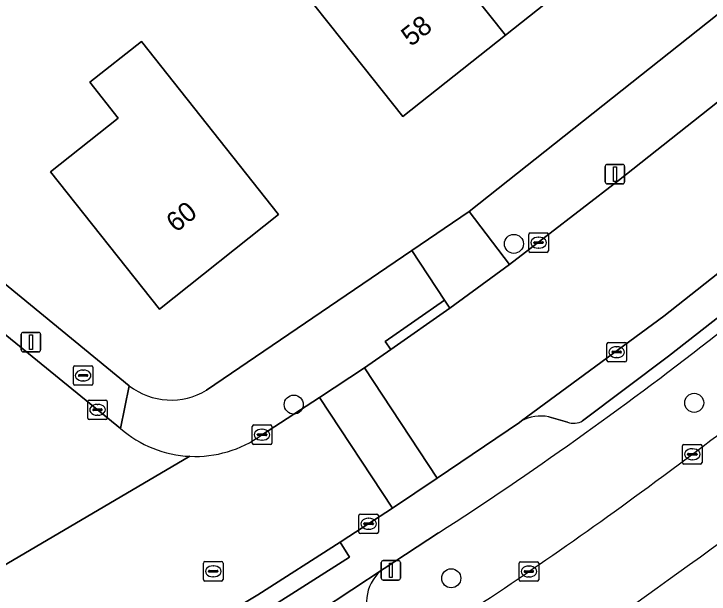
# Model space of a CAD drawing. Extents: x 159499 to 160349, y 382524 to 383273.
# Drawn here: x 159751.59 to 159787.26, y 382966.02 to 382995.78 of the extents above; entities that cross this region are included whole.
import ezdxf

# ---------------------------------------------------------------- set-up
doc = ezdxf.new("R2010")
doc.units = 0
for name, color, linetype in [('IMGEO_Boom', 7, 'Continuous'), ('IMGEO_Brandkraan', 7, 'Continuous'), ('IMGEO_Erf', 7, 'Continuous'), ('IMGEO_Groenvoorziening', 7, 'Continuous'), ('IMGEO_Kolk', 7, 'Continuous'), ('IMGEO_Lichtmast', 7, 'Continuous'), ('IMGEO_Pand', 7, 'Continuous'), ('IMGEO_Pand_nummerreeks', 7, 'Continuous'), ('IMGEO_Parkeervlak_open', 7, 'Continuous'), ('IMGEO_Rijbaan_lokaal_open', 7, 'Continuous'), ('IMGEO_Rioolput', 7, 'Continuous'), ('IMGEO_Voetpad_open', 7, 'Continuous')]:
    doc.layers.add(name, color=color, linetype=linetype)

msp = doc.modelspace()

# ---------------------------------------------------------------- linework, layer by layer
at = {"layer": 'IMGEO_Boom'}
for centre in [(159777.246, 382983.98), (159765.949, 382975.736), (159786.498, 382975.827), (159774.031, 382966.825)]:
    msp.add_circle(centre, 0.489, dxfattribs=at)
at = {"layer": 'IMGEO_Brandkraan'}
for p, q in [((159754.641, 382976.804), (159754.641, 382977.656)), ((159754.716, 382977.73), (159755.568, 382977.73)), ((159755.129, 382977.51), (159755.154, 382977.51)), ((159755.642, 382977.656), (159755.642, 382976.804)), ((159754.9, 382977.224), (159754.9, 382977.236)), ((159755.338, 382977.187), (159754.94, 382977.187)), ((159754.943, 382977.273), (159755.341, 382977.273)), ((159755.384, 382977.236), (159755.384, 382977.224)), ((159755.152, 382976.95), (159755.127, 382976.95)), ((159755.568, 382976.73), (159754.716, 382976.73))]:
    msp.add_line(p, q, dxfattribs=at)
for points in [[(159754.641, 382976.804), (159754.641, 382977.656)], [(159754.716, 382977.73), (159755.568, 382977.73)], [(159755.642, 382977.656), (159755.642, 382976.804)], [(159755.568, 382976.73), (159754.716, 382976.73)]]:
    msp.add_lwpolyline(points, dxfattribs=at)
for centre, radius, start, end in [((159754.718, 382977.654), 0.0765, 91.552, 178.448), ((159754.718, 382977.654), 0.0765, 91.552, 178.448), ((159755.566, 382977.654), 0.0765, 1.552, 88.448), ((159755.566, 382977.654), 0.0765, 1.552, 88.448), ((159754.94, 382977.233), 0.0403, 85.8775, 175.7526), ((159754.937, 382977.223), 0.0366, 178.938, 274.7102), ((159755.341, 382977.23), 0.043, 264.8664, 352.4533), ((159755.345, 382977.235), 0.0386, 1.7309, 96.639), ((159754.718, 382976.806), 0.0765, 181.552, 268.448), ((159754.718, 382976.806), 0.0765, 181.552, 268.448), ((159755.566, 382976.806), 0.0765, 271.552, 358.448), ((159755.566, 382976.806), 0.0765, 271.552, 358.448)]:
    msp.add_arc(centre, radius, start, end, dxfattribs=at)
for centre, major_axis, ratio, start_param, end_param in [((159755.128, 382977.23), (-0.387, 0.002), 0.722429, 4.712389, 7.853982), ((159755.153, 382977.23), (-0.39, 0.002), 0.717154, 1.570796, 4.712389)]:
    msp.add_ellipse(centre, major_axis=major_axis, ratio=ratio, start_param=start_param, end_param=end_param, dxfattribs=at)
at = {"layer": 'IMGEO_Erf'}
for points in [[(159761.473, 382976.471), (159772.008, 382983.648), (159774.942, 382985.649), (159793.053, 383000), (159824.858, 383025.202)], [(159738.574, 382992.221), (159738.857, 382991.989), (159741.629, 382989.716), (159757.507, 382976.697)]]:
    msp.add_lwpolyline(points, dxfattribs=at)
for points in [[(159779.201, 383007.202), (159776.897, 383005.374), (159778.957, 383002.782), (159779.951, 383001.528), (159781.162, 383000), (159782.063, 382998.864), (159776.807, 382994.694), (159771.548, 382990.52), (159768.44, 382994.437), (159765.495, 382998.147), (159764.202, 382999.777), (159764.479, 383000), (159766.41, 383001.552), (159769.487, 383003.92), (159772.486, 383006.228), (159772.407, 383006.327), (159774.63, 383008.091), (159772.911, 383010.258), (159775.283, 383012.14)], [(159765.175, 382985.49), (159759.06, 382980.638), (159753.471, 382987.681), (159756.943, 382990.435), (159755.486, 382992.271), (159758.129, 382994.368)]]:
    msp.add_lwpolyline(points, close=True, dxfattribs=at)
for centre, radius, start, end in [((159759.657, 382979.51), 3.54, 232.6136, 300.8636), ((159604.996, 383217.908), 309.102, 303.12927, 307.16526)]:
    msp.add_arc(centre, radius, start, end, dxfattribs=at)
at = {"layer": 'IMGEO_Groenvoorziening'}
msp.add_lwpolyline([(159773.383, 382969.151), (159770.582, 382967.334)], dxfattribs=at)
for centre, radius, start, end in [((159553.608, 383284.554), 388.767, 306.36737, 308.73678), ((159667.805, 383132.244), 194.283, 302.91697, 307.94175), ((159666.675, 383130.798), 197.913, 302.42764, 306.40373), ((159771.795, 382965.603), 2.113, 125.024, 298.4917)]:
    msp.add_arc(centre, radius, start, end, dxfattribs=at)
at = {"layer": 'IMGEO_Kolk'}
for p, q in [((159778.012, 382983.616), (159778.012, 382984.468)), ((159778.087, 382984.542), (159778.939, 382984.542)), ((159778.5, 382984.322), (159778.525, 382984.322)), ((159779.013, 382984.468), (159779.013, 382983.616)), ((159778.271, 382984.036), (159778.271, 382984.048)), ((159778.709, 382983.999), (159778.311, 382983.999)), ((159778.314, 382984.085), (159778.712, 382984.085)), ((159778.755, 382984.048), (159778.755, 382984.036)), ((159778.523, 382983.762), (159778.498, 382983.762)), ((159778.939, 382983.542), (159778.087, 382983.542)), ((159782.094, 382978.927), (159782.946, 382978.927)), ((159782.019, 382978.001), (159782.019, 382978.853)), ((159782.507, 382978.707), (159782.532, 382978.707)), ((159783.02, 382978.853), (159783.02, 382978.001)), ((159782.278, 382978.421), (159782.278, 382978.433)), ((159782.716, 382978.384), (159782.318, 382978.384)), ((159782.321, 382978.47), (159782.719, 382978.47)), ((159782.762, 382978.433), (159782.762, 382978.421)), ((159782.946, 382977.927), (159782.094, 382977.927)), ((159782.53, 382978.147), (159782.505, 382978.147)), ((159755.379, 382975.042), (159755.379, 382975.894)), ((159755.454, 382975.968), (159756.306, 382975.968)), ((159755.867, 382975.748), (159755.892, 382975.748)), ((159756.38, 382975.894), (159756.38, 382975.042)), ((159755.638, 382975.462), (159755.638, 382975.474)), ((159756.076, 382975.425), (159755.678, 382975.425)), ((159755.681, 382975.511), (159756.079, 382975.511)), ((159756.122, 382975.474), (159756.122, 382975.462)), ((159755.89, 382975.188), (159755.865, 382975.188)), ((159756.306, 382974.968), (159755.454, 382974.968)), ((159763.896, 382974.691), (159764.748, 382974.691)), ((159763.821, 382973.765), (159763.821, 382974.617)), ((159764.309, 382974.471), (159764.334, 382974.471)), ((159764.822, 382974.617), (159764.822, 382973.765)), ((159764.08, 382974.185), (159764.08, 382974.197)), ((159764.518, 382974.148), (159764.12, 382974.148)), ((159764.123, 382974.234), (159764.521, 382974.234)), ((159764.564, 382974.197), (159764.564, 382974.185)), ((159764.748, 382973.691), (159763.896, 382973.691)), ((159764.332, 382973.911), (159764.307, 382973.911)), ((159785.899, 382972.762), (159785.899, 382973.614)), ((159785.974, 382973.688), (159786.826, 382973.688)), ((159786.9, 382973.614), (159786.9, 382972.762)), ((159786.201, 382973.231), (159786.599, 382973.231)), ((159786.387, 382973.468), (159786.412, 382973.468)), ((159786.158, 382973.182), (159786.158, 382973.194)), ((159786.596, 382973.145), (159786.198, 382973.145)), ((159786.41, 382972.908), (159786.385, 382972.908)), ((159786.642, 382973.194), (159786.642, 382973.182)), ((159786.826, 382972.688), (159785.974, 382972.688)), ((159769.291, 382969.196), (159769.291, 382970.048)), ((159769.366, 382970.122), (159770.218, 382970.122)), ((159770.292, 382970.048), (159770.292, 382969.196)), ((159769.593, 382969.665), (159769.991, 382969.665)), ((159769.779, 382969.902), (159769.804, 382969.902)), ((159769.55, 382969.616), (159769.55, 382969.628)), ((159769.988, 382969.579), (159769.59, 382969.579)), ((159769.802, 382969.342), (159769.777, 382969.342)), ((159770.034, 382969.628), (159770.034, 382969.616)), ((159770.218, 382969.122), (159769.366, 382969.122)), ((159777.516, 382966.747), (159777.516, 382967.599)), ((159777.591, 382967.673), (159778.443, 382967.673)), ((159778.517, 382967.599), (159778.517, 382966.747)), ((159777.775, 382967.167), (159777.775, 382967.179)), ((159777.818, 382967.216), (159778.216, 382967.216)), ((159778.004, 382967.453), (159778.029, 382967.453)), ((159778.259, 382967.179), (159778.259, 382967.167)), ((159778.213, 382967.13), (159777.815, 382967.13)), ((159778.027, 382966.893), (159778.002, 382966.893)), ((159778.443, 382966.673), (159777.591, 382966.673))]:
    msp.add_line(p, q, dxfattribs=at)
for points in [[(159778.012, 382983.616), (159778.012, 382984.468)], [(159778.087, 382984.542), (159778.939, 382984.542)], [(159779.013, 382984.468), (159779.013, 382983.616)], [(159778.939, 382983.542), (159778.087, 382983.542)], [(159782.094, 382978.927), (159782.946, 382978.927)], [(159782.019, 382978.001), (159782.019, 382978.853)], [(159783.02, 382978.853), (159783.02, 382978.001)], [(159782.946, 382977.927), (159782.094, 382977.927)], [(159755.379, 382975.042), (159755.379, 382975.894)], [(159755.454, 382975.968), (159756.306, 382975.968)], [(159756.38, 382975.894), (159756.38, 382975.042)], [(159756.306, 382974.968), (159755.454, 382974.968)], [(159763.896, 382974.691), (159764.748, 382974.691)], [(159763.821, 382973.765), (159763.821, 382974.617)], [(159764.822, 382974.617), (159764.822, 382973.765)], [(159764.748, 382973.691), (159763.896, 382973.691)], [(159785.899, 382972.762), (159785.899, 382973.614)], [(159785.974, 382973.688), (159786.826, 382973.688)], [(159786.9, 382973.614), (159786.9, 382972.762)], [(159786.826, 382972.688), (159785.974, 382972.688)], [(159769.291, 382969.196), (159769.291, 382970.048)], [(159769.366, 382970.122), (159770.218, 382970.122)], [(159770.292, 382970.048), (159770.292, 382969.196)], [(159770.218, 382969.122), (159769.366, 382969.122)], [(159777.516, 382966.747), (159777.516, 382967.599)], [(159777.591, 382967.673), (159778.443, 382967.673)], [(159778.517, 382967.599), (159778.517, 382966.747)], [(159778.443, 382966.673), (159777.591, 382966.673)]]:
    msp.add_lwpolyline(points, dxfattribs=at)
for centre, radius, start, end in [((159778.089, 382984.466), 0.0765, 91.552, 178.448), ((159778.089, 382984.466), 0.0765, 91.552, 178.448), ((159778.937, 382984.466), 0.0765, 1.552, 88.448), ((159778.937, 382984.466), 0.0765, 1.552, 88.448), ((159778.311, 382984.045), 0.0403, 85.8775, 175.7526), ((159778.308, 382984.035), 0.0366, 178.938, 274.7102), ((159778.712, 382984.042), 0.043, 264.8664, 352.4533), ((159778.716, 382984.047), 0.0386, 1.7309, 96.639), ((159778.089, 382983.618), 0.0765, 181.552, 268.448), ((159778.089, 382983.618), 0.0765, 181.552, 268.448), ((159778.937, 382983.618), 0.0765, 271.552, 358.448), ((159778.937, 382983.618), 0.0765, 271.552, 358.448), ((159782.096, 382978.851), 0.0765, 91.552, 178.448), ((159782.096, 382978.851), 0.0765, 91.552, 178.448), ((159782.944, 382978.851), 0.0765, 1.552, 88.448), ((159782.944, 382978.851), 0.0765, 1.552, 88.448), ((159782.318, 382978.43), 0.0403, 85.8775, 175.7526), ((159782.315, 382978.42), 0.0366, 178.938, 274.7102), ((159782.719, 382978.427), 0.043, 264.8664, 352.4533), ((159782.723, 382978.432), 0.0386, 1.7309, 96.639), ((159782.096, 382978.003), 0.0765, 181.552, 268.448), ((159782.096, 382978.003), 0.0765, 181.552, 268.448), ((159782.944, 382978.003), 0.0765, 271.552, 358.448), ((159782.944, 382978.003), 0.0765, 271.552, 358.448), ((159755.456, 382975.892), 0.0765, 91.552, 178.448), ((159755.456, 382975.892), 0.0765, 91.552, 178.448), ((159756.304, 382975.892), 0.0765, 1.552, 88.448), ((159756.304, 382975.892), 0.0765, 1.552, 88.448), ((159755.678, 382975.471), 0.0403, 85.8775, 175.7526), ((159755.675, 382975.461), 0.0366, 178.938, 274.7102), ((159756.079, 382975.468), 0.043, 264.8664, 352.4533), ((159756.083, 382975.473), 0.0386, 1.7309, 96.639), ((159755.456, 382975.044), 0.0765, 181.552, 268.448), ((159755.456, 382975.044), 0.0765, 181.552, 268.448), ((159756.304, 382975.044), 0.0765, 271.552, 358.448), ((159756.304, 382975.044), 0.0765, 271.552, 358.448), ((159763.898, 382974.615), 0.0765, 91.552, 178.448), ((159763.898, 382974.615), 0.0765, 91.552, 178.448), ((159764.746, 382974.615), 0.0765, 1.552, 88.448), ((159764.746, 382974.615), 0.0765, 1.552, 88.448), ((159764.12, 382974.194), 0.0403, 85.8775, 175.7526), ((159764.117, 382974.184), 0.0366, 178.938, 274.7102), ((159764.521, 382974.191), 0.043, 264.8664, 352.4533), ((159764.525, 382974.196), 0.0386, 1.7309, 96.639), ((159763.898, 382973.767), 0.0765, 181.552, 268.448), ((159763.898, 382973.767), 0.0765, 181.552, 268.448), ((159764.746, 382973.767), 0.0765, 271.552, 358.448), ((159764.746, 382973.767), 0.0765, 271.552, 358.448), ((159785.976, 382973.612), 0.0765, 91.552, 178.448), ((159785.976, 382973.612), 0.0765, 91.552, 178.448), ((159786.824, 382973.612), 0.0765, 1.552, 88.448), ((159786.824, 382973.612), 0.0765, 1.552, 88.448), ((159786.198, 382973.191), 0.0403, 85.8775, 175.7526), ((159786.603, 382973.193), 0.0386, 1.7309, 96.639), ((159786.195, 382973.181), 0.0366, 178.938, 274.7102), ((159786.599, 382973.188), 0.043, 264.8664, 352.4533), ((159785.976, 382972.764), 0.0765, 181.552, 268.448), ((159785.976, 382972.764), 0.0765, 181.552, 268.448), ((159786.824, 382972.764), 0.0765, 271.552, 358.448), ((159786.824, 382972.764), 0.0765, 271.552, 358.448), ((159769.368, 382970.046), 0.0765, 91.552, 178.448), ((159769.368, 382970.046), 0.0765, 91.552, 178.448), ((159770.216, 382970.046), 0.0765, 1.552, 88.448), ((159770.216, 382970.046), 0.0765, 1.552, 88.448), ((159769.59, 382969.625), 0.0403, 85.8775, 175.7526), ((159769.995, 382969.627), 0.0386, 1.7309, 96.639), ((159769.587, 382969.615), 0.0366, 178.938, 274.7102), ((159769.991, 382969.622), 0.043, 264.8664, 352.4533), ((159769.368, 382969.198), 0.0765, 181.552, 268.448), ((159769.368, 382969.198), 0.0765, 181.552, 268.448), ((159770.216, 382969.198), 0.0765, 271.552, 358.448), ((159770.216, 382969.198), 0.0765, 271.552, 358.448), ((159777.593, 382967.597), 0.0765, 91.552, 178.448), ((159777.593, 382967.597), 0.0765, 91.552, 178.448), ((159778.441, 382967.597), 0.0765, 1.552, 88.448), ((159778.441, 382967.597), 0.0765, 1.552, 88.448), ((159777.815, 382967.176), 0.0403, 85.8775, 175.7526), ((159777.812, 382967.166), 0.0366, 178.938, 274.7102), ((159778.216, 382967.173), 0.043, 264.8664, 352.4533), ((159778.22, 382967.178), 0.0386, 1.7309, 96.639), ((159777.593, 382966.749), 0.0765, 181.552, 268.448), ((159777.593, 382966.749), 0.0765, 181.552, 268.448), ((159778.441, 382966.749), 0.0765, 271.552, 358.448), ((159778.441, 382966.749), 0.0765, 271.552, 358.448)]:
    msp.add_arc(centre, radius, start, end, dxfattribs=at)
for centre, major_axis, ratio, start_param, end_param in [((159778.499, 382984.042), (-0.387, 0.002), 0.722429, 4.712389, 7.853982), ((159778.524, 382984.042), (-0.39, 0.002), 0.717154, 1.570796, 4.712389), ((159782.506, 382978.427), (-0.387, 0.002), 0.722429, 4.712389, 7.853982), ((159782.531, 382978.427), (-0.39, 0.002), 0.717154, 1.570796, 4.712389), ((159755.866, 382975.468), (-0.387, 0.002), 0.722429, 4.712389, 7.853982), ((159755.891, 382975.468), (-0.39, 0.002), 0.717154, 1.570796, 4.712389), ((159764.308, 382974.191), (-0.387, 0.002), 0.722429, 4.712389, 7.853982), ((159764.333, 382974.191), (-0.39, 0.002), 0.717154, 1.570796, 4.712389), ((159786.386, 382973.188), (-0.387, 0.002), 0.722429, 4.712389, 7.853982), ((159786.411, 382973.188), (-0.39, 0.002), 0.717154, 1.570796, 4.712389), ((159769.778, 382969.622), (-0.387, 0.002), 0.722429, 4.712389, 7.853982), ((159769.803, 382969.622), (-0.39, 0.002), 0.717154, 1.570796, 4.712389), ((159778.003, 382967.173), (-0.387, 0.002), 0.722429, 4.712389, 7.853982), ((159778.028, 382967.173), (-0.39, 0.002), 0.717154, 1.570796, 4.712389)]:
    msp.add_ellipse(centre, major_axis=major_axis, ratio=ratio, start_param=start_param, end_param=end_param, dxfattribs=at)
at = {"layer": 'IMGEO_Lichtmast'}
for p, q in [((159781.934, 382987.156), (159781.934, 382987.956)), ((159781.934, 382987.956), (159781.934, 382987.156)), ((159782.034, 382988.056), (159782.824, 382988.056)), ((159782.824, 382988.056), (159782.034, 382988.056)), ((159782.924, 382987.956), (159782.924, 382987.156)), ((159782.924, 382987.156), (159782.924, 382987.956)), ((159782.824, 382987.056), (159782.034, 382987.056)), ((159782.034, 382987.056), (159782.824, 382987.056)), ((159751.966, 382978.54), (159751.966, 382979.34)), ((159751.966, 382979.34), (159751.966, 382978.54)), ((159752.066, 382979.44), (159752.856, 382979.44)), ((159752.856, 382979.44), (159752.066, 382979.44)), ((159752.956, 382979.34), (159752.956, 382978.54)), ((159752.956, 382978.54), (159752.956, 382979.34)), ((159752.856, 382978.44), (159752.066, 382978.44)), ((159752.066, 382978.44), (159752.856, 382978.44)), ((159770.436, 382966.833), (159770.436, 382967.633)), ((159770.436, 382967.633), (159770.436, 382966.833)), ((159770.536, 382967.733), (159771.326, 382967.733)), ((159771.326, 382967.733), (159770.536, 382967.733)), ((159771.426, 382967.633), (159771.426, 382966.833)), ((159771.426, 382966.833), (159771.426, 382967.633)), ((159771.326, 382966.733), (159770.536, 382966.733)), ((159770.536, 382966.733), (159771.326, 382966.733))]:
    msp.add_line(p, q, dxfattribs=at)
for points in [[(159782.354, 382987.931), (159782.504, 382987.931), (159782.504, 382987.181), (159782.354, 382987.181), (159782.354, 382987.931)], [(159752.386, 382979.315), (159752.536, 382979.315), (159752.536, 382978.565), (159752.386, 382978.565), (159752.386, 382979.315)], [(159770.856, 382967.608), (159771.006, 382967.608), (159771.006, 382966.858), (159770.856, 382966.858), (159770.856, 382967.608)]]:
    msp.add_lwpolyline(points, dxfattribs=at)
for centre, start, end in [((159782.034, 382987.956), 90, 180), ((159782.034, 382987.956), 90, 180), ((159782.824, 382987.956), 0, 90), ((159782.824, 382987.956), 360, 90), ((159782.034, 382987.156), 180, 270), ((159782.034, 382987.156), 180, 270), ((159782.824, 382987.156), 270, 0), ((159782.824, 382987.156), 270, 0), ((159752.066, 382979.34), 90, 180), ((159752.066, 382979.34), 90, 180), ((159752.856, 382979.34), 0, 90), ((159752.856, 382979.34), 360, 90), ((159752.066, 382978.54), 180, 270), ((159752.066, 382978.54), 180, 270), ((159752.856, 382978.54), 270, 0), ((159752.856, 382978.54), 270, 0), ((159770.536, 382967.633), 90, 180), ((159770.536, 382967.633), 90, 180), ((159771.326, 382967.633), 0, 90), ((159771.326, 382967.633), 360, 90), ((159770.536, 382966.833), 180, 270), ((159770.536, 382966.833), 180, 270), ((159771.326, 382966.833), 270, 0), ((159771.326, 382966.833), 270, 0)]:
    msp.add_arc(centre, 0.1, start, end, dxfattribs=at)
at = {"layer": 'IMGEO_Pand'}
for points in [[(159776.897, 383005.374), (159779.201, 383007.202), (159775.283, 383012.14), (159772.911, 383010.258), (159774.63, 383008.091), (159772.407, 383006.327), (159772.486, 383006.228), (159769.487, 383003.92), (159770.72, 383002.365), (159772.596, 383000), (159776.807, 382994.694), (159782.063, 382998.864), (159781.162, 383000), (159779.951, 383001.528), (159778.957, 383002.782)], [(159769.487, 383003.92), (159766.41, 383001.552), (159764.479, 383000), (159764.202, 382999.777), (159765.495, 382998.147), (159768.44, 382994.437), (159771.548, 382990.52), (159776.807, 382994.694), (159772.596, 383000), (159770.72, 383002.365)], [(159759.06, 382980.638), (159765.175, 382985.49), (159758.129, 382994.368), (159755.486, 382992.271), (159756.943, 382990.435), (159753.471, 382987.681)]]:
    msp.add_lwpolyline(points, close=True, dxfattribs=at)
at = {"layer": 'IMGEO_Parkeervlak_open'}
for points in [[(159816.646, 383005.334), (159784.946, 382980.27), (159777.634, 382974.895)], [(159780.772, 382974.903), (159785.179, 382978.223), (159797.492, 382987.853), (159799.938, 382989.792), (159812.811, 383000), (159815.625, 383002.231)], [(159779.034, 382975.108), (159779.994, 382974.834)]]:
    msp.add_lwpolyline(points, dxfattribs=at)
for centre, radius, start, end in [((159778.624, 382973.096), 2.053, 78.4794, 118.8222), ((159780.308, 382975.71), 0.931, 250.2655, 299.8709)]:
    msp.add_arc(centre, radius, start, end, dxfattribs=at)
at = {"layer": 'IMGEO_Rijbaan_lokaal_open'}
for points in [[(159816.646, 383005.334), (159818.638, 383006.917), (159827.27, 383013.774), (159828.26, 383014.561), (159823.977, 383019.969), (159810.572, 383009.347), (159805.481, 383005.321), (159798.752, 383000), (159794.355, 382996.523), (159794.077, 382996.304), (159788.426, 382991.835), (159782.608, 382987.234), (159777.025, 382982.921), (159773.96, 382980.682), (159770.933, 382978.556), (159769.571, 382977.626), (159773.313, 382971.955), (159777.531, 382974.823), (159777.634, 382974.895), (159784.946, 382980.27)], [(159769.571, 382977.626), (159767.275, 382976.094), (159771.016, 382970.427), (159773.313, 382971.955)]]:
    msp.add_lwpolyline(points, close=True, dxfattribs=at)
for points in [[(159757.061, 382974.504), (159740.39, 382988.088), (159737.539, 382990.411), (159736.991, 382990.857)], [(159696.099, 382935.301), (159699.946, 382936.7), (159700.852, 382937.031), (159701.086, 382937.144), (159718.304, 382943.378), (159720.187, 382944.082), (159733.185, 382949.569), (159742.119, 382953.821), (159754.023, 382960.12), (159754.237, 382960.246), (159754.457, 382960.36), (159758.932, 382962.886), (159764.112, 382965.984), (159768.323, 382968.671), (159768.781, 382968.963), (159771.016, 382970.427), (159767.275, 382976.094), (159764.296, 382974.173)], [(159760.621, 382973.082), (159750.62, 382967.229)], [(159750.62, 382967.229), (159760.621, 382973.082)], [(159770.582, 382967.334), (159767.273, 382965.143), (159772.631, 382958.244), (159773.929, 382959.054)]]:
    msp.add_lwpolyline(points, dxfattribs=at)
for centre, radius, start, end in [((159553.608, 383284.554), 388.767, 306.36737, 308.73678), ((159760.89, 382978.923), 5.847, 229.0893, 267.3634), ((159760.891, 382978.908), 5.832, 267.3469, 305.7224), ((159666.675, 383130.798), 197.913, 302.42764, 306.40373), ((159604.996, 383217.908), 309.102, 303.12927, 307.16526), ((159771.795, 382965.603), 2.113, 125.024, 298.4917)]:
    msp.add_arc(centre, radius, start, end, dxfattribs=at)
at = {"layer": 'IMGEO_Rioolput'}
for p, q in [((159761.318, 382966.758), (159761.318, 382967.61)), ((159761.393, 382967.684), (159762.245, 382967.684)), ((159762.319, 382967.61), (159762.319, 382966.758)), ((159761.577, 382967.178), (159761.577, 382967.19)), ((159761.62, 382967.227), (159762.018, 382967.227)), ((159761.806, 382967.464), (159761.831, 382967.464)), ((159762.061, 382967.19), (159762.061, 382967.178)), ((159762.015, 382967.141), (159761.617, 382967.141)), ((159761.829, 382966.904), (159761.804, 382966.904)), ((159762.245, 382966.684), (159761.393, 382966.684))]:
    msp.add_line(p, q, dxfattribs=at)
for points in [[(159761.318, 382966.758), (159761.318, 382967.61)], [(159761.393, 382967.684), (159762.245, 382967.684)], [(159762.319, 382967.61), (159762.319, 382966.758)], [(159762.245, 382966.684), (159761.393, 382966.684)]]:
    msp.add_lwpolyline(points, dxfattribs=at)
for centre, radius, start, end in [((159761.395, 382967.608), 0.0765, 91.552, 178.448), ((159761.395, 382967.608), 0.0765, 91.552, 178.448), ((159762.243, 382967.608), 0.0765, 1.552, 88.448), ((159762.243, 382967.608), 0.0765, 1.552, 88.448), ((159761.617, 382967.187), 0.0403, 85.8775, 175.7526), ((159761.614, 382967.177), 0.0366, 178.938, 274.7102), ((159762.018, 382967.184), 0.043, 264.8664, 352.4533), ((159762.022, 382967.189), 0.0386, 1.7309, 96.639), ((159761.395, 382966.76), 0.0765, 181.552, 268.448), ((159761.395, 382966.76), 0.0765, 181.552, 268.448), ((159762.243, 382966.76), 0.0765, 271.552, 358.448), ((159762.243, 382966.76), 0.0765, 271.552, 358.448)]:
    msp.add_arc(centre, radius, start, end, dxfattribs=at)
for centre, major_axis, ratio, start_param, end_param in [((159761.805, 382967.184), (-0.387, 0.002), 0.722429, 4.712389, 7.853982), ((159761.83, 382967.184), (-0.39, 0.002), 0.717154, 1.570796, 4.712389)]:
    msp.add_ellipse(centre, major_axis=major_axis, ratio=ratio, start_param=start_param, end_param=end_param, dxfattribs=at)
at = {"layer": 'IMGEO_Voetpad_open'}
for points in [[(159823.977, 383019.969), (159826.116, 383021.665), (159831.353, 383025.815), (159830.707, 383026.63), (159830.825, 383029.654), (159824.98, 383025.268), (159824.858, 383025.202), (159793.053, 383000), (159774.942, 382985.649), (159777.025, 382982.921), (159782.608, 382987.234), (159788.426, 382991.835), (159787.781, 382992.651), (159793.432, 382997.12), (159794.077, 382996.304), (159794.355, 382996.523), (159798.752, 383000), (159805.481, 383005.321), (159804.836, 383006.137), (159809.927, 383010.163), (159810.572, 383009.347)], [(159741.629, 382989.716), (159740.39, 382988.088), (159757.061, 382974.504), (159757.507, 382976.697)], [(159772.008, 382983.648), (159773.686, 382981.099), (159773.96, 382980.682), (159777.025, 382982.921), (159774.942, 382985.649)], [(159770.933, 382978.556), (159773.96, 382980.682), (159773.686, 382981.099), (159770.648, 382978.965)], [(159768.807, 382967.912), (159768.323, 382968.671), (159764.112, 382965.984), (159758.932, 382962.886), (159759.394, 382962.114), (159762.205, 382963.795), (159764.585, 382965.218)]]:
    msp.add_lwpolyline(points, close=True, dxfattribs=at)
for points in [[(159787.262, 382979.025), (159796.969, 382986.685), (159798.414, 382987.84), (159800.978, 382984.561), (159802.862, 382986.037), (159800.322, 382989.329), (159799.938, 382989.792), (159797.492, 382987.853), (159785.179, 382978.223), (159780.772, 382974.903)], [(159770.933, 382978.556), (159770.648, 382978.965), (159773.686, 382981.099), (159772.008, 382983.648), (159761.473, 382976.471)], [(159764.296, 382974.173), (159767.275, 382976.094), (159769.571, 382977.626), (159770.933, 382978.556)], [(159757.507, 382976.697), (159757.061, 382974.504)], [(159779.994, 382974.834), (159779.034, 382975.108)], [(159777.634, 382974.895), (159777.531, 382974.823), (159773.313, 382971.955), (159771.016, 382970.427), (159768.781, 382968.963), (159768.323, 382968.671), (159768.807, 382967.912), (159764.585, 382965.218), (159762.205, 382963.795), (159762.986, 382962.489), (159767.273, 382965.143), (159770.582, 382967.334), (159773.383, 382969.151)]]:
    msp.add_lwpolyline(points, dxfattribs=at)
for centre, radius, start, end in [((159667.805, 383132.244), 194.283, 302.91697, 307.94175), ((159759.657, 382979.51), 3.54, 232.6136, 300.8636), ((159778.624, 382973.096), 2.053, 78.4794, 118.8222), ((159780.308, 382975.71), 0.931, 250.2655, 299.8709), ((159760.89, 382978.923), 5.847, 229.0893, 267.3634), ((159760.891, 382978.908), 5.832, 267.3469, 305.7224)]:
    msp.add_arc(centre, radius, start, end, dxfattribs=at)

# ---------------------------------------------------------------- texts
at = {"layer": 'IMGEO_Pand_nummerreeks'}
for s, rotation, p in [('58', 38.4397, (159771.966, 382994.069)), ('60', 38.4305, (159759.906, 382984.527))]:
    msp.add_text(s, height=1, rotation=rotation, dxfattribs=at).set_placement(p)

doc.saveas('drawing.dxf')
